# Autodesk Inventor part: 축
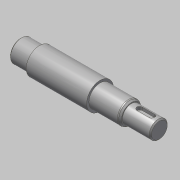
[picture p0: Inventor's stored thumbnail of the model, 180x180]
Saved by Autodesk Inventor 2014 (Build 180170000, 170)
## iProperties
Created: 2016-06
Part Number: 축
Material: 강철, 연강
Document SubType Name: Modeling
Designer: mduedu
Density: 7.86 g/cm^3
Appearance: 강철
Author: mduedu
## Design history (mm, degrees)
sketch "스케치1"
  geometry: L1 (-62, 0)-(62, 0); L2 (-62, 0)-(-62, 10); L3 (-62, 10)-(-45, 10); L4 (-45, 10)-(-45, 12); L5 (-45, 12)-(9, 12); L6 (9, 12)-(9, 10); L7 (9, 10)-(37, 10); L8 (37, 10)-(37, 8); L9 (37, 8)-(62, 8); L10 (62, 8)-(62, 0); 2 further points
  constraints: 20 end point, 5 parallel, 2 perpendicular, 1 coincident, 1 collinear, 1 horizontal, 1 midpoint, 1 vertical
  dimensions: "d0" = 124 distance of L1.start L1.end; "d2" = 16 diameter of L9 L1; "d3" = 20 diameter of L7 L1; "d4" = 24 diameter of L5 L1; "d5" = 20 diameter of L3 L1; "d6" = 17 distance of L2.end L3.end; "d7" = 25 distance of L8.end L9.end; "d8" = 53 distance from line of L5.end L10
revolve "회전1" sketch "스케치1" stored, may be unused: angle "d9" = 90 deg
chamfer "모따기1" distance "d10" = 2; stored, may be unused: second distance "d11" = 2, angle "d12" = 30 deg
fillet "모깎기1" dims "d13" = 2
node "작업 평면1"
sketch "스케치2"
  geometry: L1 (-5, 2.5)-(6, 2.5); L2 (6, -2.5)-(-5, -2.5); L3 (-5, 0)-(6, 0); L4 (-12.5, 8.845)-(-12.5, -8.845) reference; A1 r 2.5 centre (-5, 0) between (-5, 2.5) and (-5, -2.5); A2 r 2.5 centre (6, 0) between (6, -2.5) and (6, 2.5); 1 further point
  constraints: 6 end point, 4 point on circle, 3 tangent, 2 centre point, 2 parallel, 1 horizontal, 1 horizontal alignment
  dimensions: "d14" = 5 distance edge to line of A1 L4; "d15" = 5 distance between parallel lines of L2 L1; "d16" = 16 dimension on A2 A1
extrude "돌출1" cut sketch "스케치2" distance "d17" = 3; taper "d18" = 0 deg
chamfer "모따기2" distance "d19" = 1; stored, may be unused: second distance "d20" = 2, angle "d21" = 30 deg
sketch "스케치3"
  geometry: L1 (-37, -8)-(-61, -8) reference; L2 (-62, -7)-(-62, 7) reference; L3 (-38.5, -8)-(-40, -6.5); L4 (-40, -6.5)-(-40, -8); L5 (-38.5, -8)-(-40, -8); 1 further point
  constraints: 6 end point, 2 point on line, 1 collinear, 1 vertical
  dimensions: "d22" = 45 deg angle of L4 L3; "d23" = 22 distance between parallel lines of L2 L4; "d24" = 3 diameter of L3.start L4
revolve "회전2" stored, may be unused: angle "d25" = 90 deg
node "작업점1"
sketch "스케치4"
  geometry: 1 further point
hole "구멍1" sketch "스케치4" at (0, 0) diameter "d26" = 3.242; stored, may be unused: countersink angle "d30" = 90 deg, drill point angle "d32" = 120 deg; dims "d27" = 8, "d28" = 4, "d29" = 2, "d31" = 11
chamfer "모따기3" distance "d33" = 2; stored, may be unused: second distance "d34" = 2, angle "d35" = 30 deg
node "솔리드1"
